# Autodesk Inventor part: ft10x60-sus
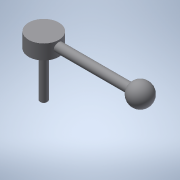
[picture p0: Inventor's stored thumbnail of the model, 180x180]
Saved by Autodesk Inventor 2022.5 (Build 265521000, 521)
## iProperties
Created: 2016-12
Part Number: ft10x60-sus
Material: 一般
Document SubType Name: Modeling
Designer: imaocorp
Density: 1 g/cm^3
Appearance: 既定
Author: imaocorp
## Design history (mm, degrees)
node "ft10x60-sus.x_t1"
node "ft10x60-sus"
node "Base1"
